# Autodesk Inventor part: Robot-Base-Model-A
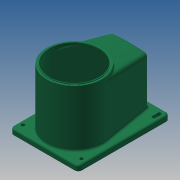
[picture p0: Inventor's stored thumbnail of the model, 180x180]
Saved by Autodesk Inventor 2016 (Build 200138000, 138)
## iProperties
Shininess: 21.0
Length Units: 11269
Angle Units: 11279
Time Units: 11290
Mass Units: 11283
Length Display Precision: 3
Angle Display Precision: 2
Created: 2001-08
Part Number: Robot-Base-Model-A
Document SubType Name: ﾓﾃﾞﾘﾝｸﾞ
Designer: Administrator
Density: 1 g/cm^3
Material: Generic
Mass: 357.747 g
Surface Area: 3585.3 cm^2
Volume: 357.747 cm^3
Appearance: Sea Green
Density: 0.0
Volumn: 0.0
Area: 0.0
PropertySet Name: Model Information
Control State: 0
Master: False
Checked Out: False
Author: Administrator
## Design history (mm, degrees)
node "Center-Work Plane"
fillet "Chamfer1" dims "d14" = 10
fillet "Chamfer2" dims "d15" = 5
fillet "Chamfer3" dims "d16" = 10
fillet "Chamfer4" dims "d30" = 5
sketch "Sketch6"
  geometry: L1 (80, 152.5)-(80, 137.5); L2 (84.5, 152.5)-(84.5, 137.5); L3 (75.5, 137.5)-(75.5, 152.5); L4 (-80, 152.5)-(-80, 137.5); L5 (-75.5, 152.5)-(-75.5, 137.5); L6 (-84.5, 137.5)-(-84.5, 152.5); A1 r 4.5 centre (80, 152.5) between (84.5, 152.5) and (75.5, 152.5); A2 r 4.5 centre (80, 137.5) between (75.5, 137.5) and (84.5, 137.5); A3 r 4.5 centre (-80, 152.5) between (-75.5, 152.5) and (-84.5, 152.5); A4 r 4.5 centre (-80, 137.5) between (-84.5, 137.5) and (-75.5, 137.5); 3 further points
  constraints: 16 end point, 8 point on circle, 8 tangent, 4 centre point, 4 parallel, 2 midpoint, 1 equal radius, 1 vertical
  dimensions: "d35" = 4.5 radius of A2; "d36" = 15 distance of L1.start L1.end
extrude "Extrusion5" cut sketch "Sketch6" stored distance "d37" = 10; taper "d38" = 0 deg
shell "Shell1" dims "d34" = 2
body "Solid1"
sketch "Sketch1"
  geometry: L1 (-93, 168)-(93, 168); L2 (93, 168)-(93, -82); L3 (93, -82)-(-93, -82); L4 (-93, -82)-(-93, 168); L5 (-93, 0)-(93, 0); L6 (0, 168)-(0, -82); 2 further points
  constraints: 12 end point, 3 midpoint, 3 point on line, 2 parallel, 1 coincident, 1 horizontal, 1 perpendicular, 1 other
  dimensions: "d0" = 250 distance of L3.end L1.start; "d1" = 186 distance of L1.start L1.end; "d2" = 82 distance between parallel lines of L3 L5
extrude "Extrusion1" new body sketch "Sketch1" distance "d3" = 15; taper "d4" = 0 deg
sketch "Sketch2"
  geometry: C1 r 75 at (0, 0)
  constraints: 1 centre point
  dimensions: "d5" = 150 diameter of C1
extrude "Extrusion2" join sketch "Sketch2" distance "d6" = 155; taper "d7" = 0 deg
sketch "Sketch3"
  geometry: L1 (-93, 168)-(93, 168) reference; L2 (-50, 153)-(50, 153); L3 (0, 197.064)-(0, -91.178); L4 (50, 153)-(73.933, 12.603); L5 (-50, 153)-(-73.933, 12.603); L6 (-73.933, 12.603)-(73.933, 12.603); A1 r 75 centre (0, 0) between (73.933, 12.603) and (-73.933, 12.603) reference
  constraints: 10 end point, 2 point on circle, 2 tangent, 1 parallel, 1 perpendicular, 1 point on line
  dimensions: "d8" = 50 distance from line of L2.start L3; "d9" = 50 distance from line of L2.end L3; "d10" = 15 distance between parallel lines of L2 L1
extrude "Extrusion3" join sketch "Sketch3" distance "d11" = 145; taper "d12" = 0 deg
feature "FaceDraft" dims angle "d13" = 10 deg
sketch "Sketch4"
  geometry: L1 (-93, -72)-(-93, 158) reference; L2 (-80, 145)-(80, 145); L3 (-80, 145)-(-80, -173.228); L4 (80, 145)-(80, -173.228); L5 (-80, -60)-(80, -60); L6 (0, 145)-(0, -60); 5 further points
  constraints: 10 end point, 4 coincident, 3 point on line, 2 midpoint, 2 parallel, 2 perpendicular, 1 other
  dimensions: "d19" = 160 distance between parallel lines of L4 L3; "d21" = 205 distance between parallel lines of L5 L2; "d22" = 60 distance from line of L5 point (0, 0)
hole "Hole1" sketch "Sketch4" diameter "d23" = 9; stored, may be unused: countersink angle "d27" = 82 deg, drill point angle "d29" = 118 deg; dims "d24" = 6, "d25" = 4, "d26" = 2, "d28" = 8
sketch "Sketch5"
  geometry: C1 r 75 at (0, 0) reference; C2 r 70 at (0, 0)
  constraints: 1 centre point
  dimensions: "d31" = 5 radial gap between concentric circles of C1 C2
extrude "Extrusion4" join sketch "Sketch5" distance "d32" = 2; taper "d33" = 0 deg
